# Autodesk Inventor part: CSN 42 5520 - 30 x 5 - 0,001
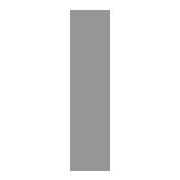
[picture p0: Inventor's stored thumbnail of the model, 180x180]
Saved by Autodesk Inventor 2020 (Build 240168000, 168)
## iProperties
IsCustomPart: 1
Created: 2019-01
Part Number: CSN 42 5520 - 30 x 5 - 0,001
Material: Ocel, měkká
Description: Tyč
Document SubType Name: Modeling
Standard: CSN 42 5520
Designer: doma
Standards Organization: CSN
Language: cs-CZ
Size Designation: 30 x 5 - 0,001
Categories: <MemberInstance><Categories><Category DisplayName="Konstrukční profily" InternalName="089c4875-fa83-4c05-b084-43b9cc11f5ed" Mnemonic="GRDR"><CategoryParameter D
Stock Number: 30 x 5
Density: 7.85 g/cm^3
Appearance: Pololeštěná
G_L: 0,001 mm
Author: doma
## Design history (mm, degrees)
node "Počáteční rovina"
node "Koncová rovina"
sketch "Náčrt"
  geometry: L1 (2.5, -15)-(-2.5, -15); L2 (-2.5, -15)-(-2.5, 15); L3 (-2.5, 15)-(2.5, 15); L4 (2.5, 15)-(2.5, -15); L5 (-6, 0)-(8, 0); L6 (0, -30)-(0, 40); L7 (0, 54)-(0, -44) reference; L8 (-9.2, 0)-(13.2, 0) reference
  constraints: 12 end point, 2 collinear, 2 parallel, 1 horizontal, 1 perpendicular
  dimensions: "d0" = 30 distance between parallel lines of L3 L1 (= G_W); "d1" = 5 distance between parallel lines of L4 L2 (= G_H); "d4" = 2.5 distance between parallel lines of L6 L4 (= 0.5 x d1); "d5" = 15 distance between parallel lines of L5 L3 (= 0.5 x d0)
extrude "Těleso" new body sketch "Náčrt" stored distance "d2" = 320; taper "d3" = 0 deg
node "Driven Length"
  sketch "Sketch3"
    geometry: L1 (0, 0)-(10, 0) reference
    constraints: 2 end point, 1 horizontal
  workplane "Work Plane3"
  sketch "Sketch4"
    geometry: L1 (-2, 0)-(12, 0) reference; L2 (-2, 0.001)-(12, 0.001) reference
    dimensions: "d9" = 0.001 distance between parallel lines of L1 L2 (derived)
body "Solid1"
other parameters: "G_W" = 30 [user parameter; used in 1 equation term], "G_H" = 5 [user parameter; used in 1 equation term], "G_L" = 0.001 (= d9) [user parameter], "G_OFFSET_START" = 0 [user parameter; used in 1 equation term], "G_OFFSET_END" = 0 [user parameter; used in 1 equation term], "d6" = 0 (computed from G_OFFSET_START), "d7" = 0.001 (= G_OFFSET_END + B_L), "B_L" = 0.001 [user parameter; used in 1 equation term], "d8" = 90 deg
